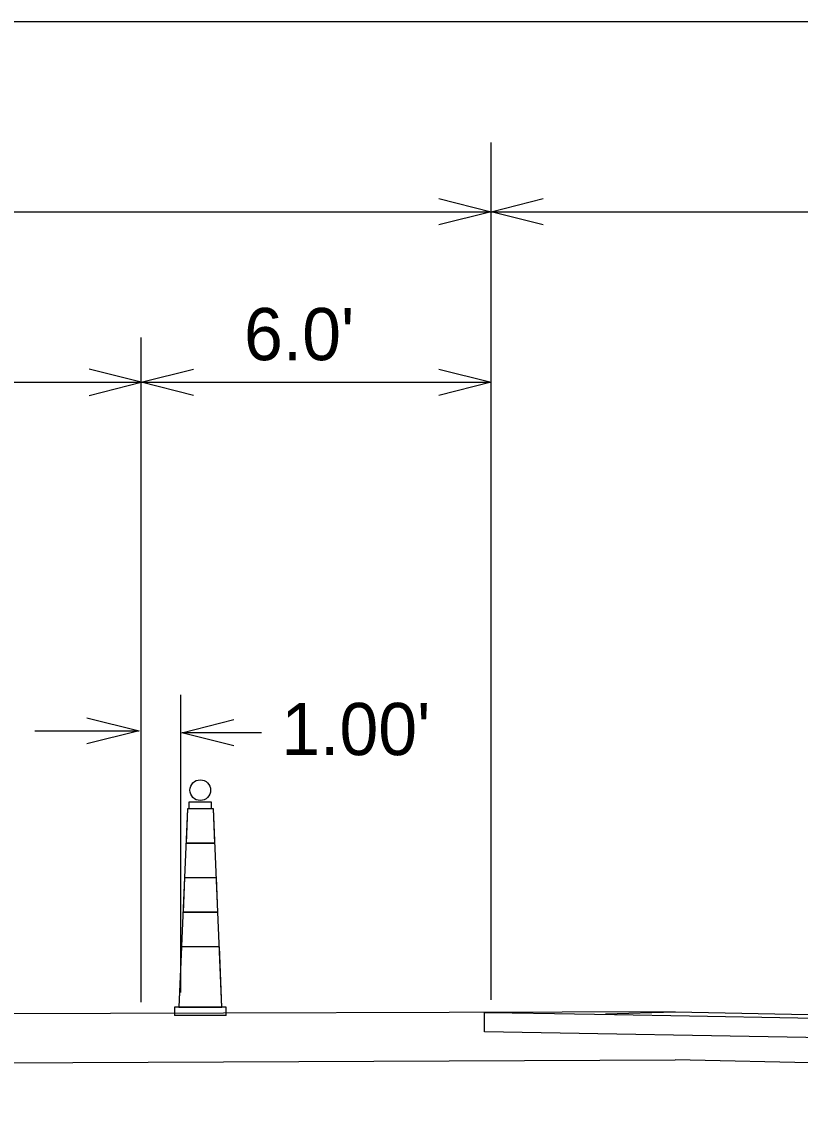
# Model space of a CAD drawing. Extents: x 10133 to 81668, y 4692 to 11018.
# Drawn here: x 29468.4 to 29807.5, y 5951 to 6420.8 of the extents above; entities that cross this region are included whole.
import ezdxf

# ---------------------------------------------------------------- set-up
doc = ezdxf.new("R2010")
doc.units = 0
for name, color, linetype in [('Level 7', 7, 'Continuous'), ('PavementRemovalStage1', 7, 'Continuous'), ('Stage_Construction Traffic Control', 7, 'Continuous')]:
    doc.layers.add(name, color=color, linetype=linetype)

msp = doc.modelspace()

# ---------------------------------------------------------------- linework, layer by layer
at = {"layer": 'Level 7'}
for p, q in [((28720.67, 6420.77), (30624.93, 6420.77)), ((29672.8, 5995.19), (29672.8, 6368.21)), ((28720.67, 6338.05), (29672.8, 6338.05)), ((28879.42, 6338.05), (29672.8, 6338.05)), ((29672.8, 6338.05), (30624.93, 6338.05)), ((29520.54, 5994.2), (29520.54, 6283.36)), ((29295.04, 6263.84), (29672.8, 6263.84)), ((29537.75, 5998.41), (29537.75, 6127.84)), ((29474.13, 6112.15), (29519.55, 6112.15)), ((29572.86, 6111.38), (29538.17, 6111.38)), ((29722.56, 5989.14), (29752.89, 5989.91)), ((28779.45, 5964.82), (29752.89, 5969)), ((30566.15, 5950.97), (29752.89, 5969))]:
    msp.add_line(p, q, dxfattribs=at)
for points in [[(29650.09, 6343.73), (29672.8, 6338.05), (29650.09, 6332.38)], [(29695.51, 6332.38), (29672.8, 6338.05), (29695.51, 6343.73)], [(29497.83, 6258.16), (29520.54, 6263.84), (29497.83, 6269.52)], [(29543.25, 6258.16), (29520.54, 6263.84), (29543.25, 6269.52)], [(29650.09, 6269.52), (29672.8, 6263.84), (29650.09, 6258.16)], [(29496.84, 6117.83), (29519.55, 6112.15), (29496.84, 6106.48)], [(29560.88, 6105.7), (29538.17, 6111.38), (29560.88, 6117.06)]]:
    msp.add_lwpolyline(points, dxfattribs=at)
at = {"layer": 'PavementRemovalStage1'}
for p, q in [((29752.89, 5989.91), (28720.67, 5987.21)), ((29669.91, 5981.22), (29669.92, 5985.7)), ((29752.89, 5989.91), (30624.93, 5973.37)), ((30100.93, 5973.7), (29669.91, 5981.22))]:
    msp.add_line(p, q, dxfattribs=at)
msp.add_lwpolyline([(29669.92, 5985.7), (29669.95, 5989.69), (29681.97, 5989.48), (29700.48, 5989.17), (29726.48, 5988.72), (29759.21, 5988.16), (29806.37, 5987.36), (29871.61, 5986.24), (29906.06, 5985.65), (30103.23, 5982.29)], dxfattribs=at)
at = {"layer": 'Stage_Construction Traffic Control'}
for p, q in [((29540.67, 6078.28), (29536.92, 5992.03)), ((29540.67, 6078.28), (29540.02, 6063.28)), ((29551.92, 6078.28), (29540.67, 6078.28)), ((29551.92, 6078.28), (29540.67, 6078.28)), ((29555.67, 5992.03), (29551.92, 6078.28)), ((29552.57, 6063.28), (29551.92, 6078.28)), ((29552.57, 6063.28), (29540.02, 6063.28)), ((29540.02, 6063.28), (29552.57, 6063.28)), ((29539.37, 6048.28), (29538.71, 6033.28)), ((29553.23, 6048.28), (29539.37, 6048.28)), ((29553.23, 6048.28), (29539.37, 6048.28)), ((29553.88, 6033.28), (29553.23, 6048.28)), ((29553.88, 6033.28), (29538.71, 6033.28)), ((29538.71, 6033.28), (29553.88, 6033.28)), ((29538.06, 6018.28), (29536.92, 5992.03)), ((29554.53, 6018.28), (29538.06, 6018.28)), ((29554.53, 6018.28), (29538.06, 6018.28)), ((29555.67, 5992.03), (29554.53, 6018.28)), ((29557.55, 5992.03), (29535.05, 5992.03)), ((29535.05, 5992.03), (29535.05, 5988.28)), ((29536.92, 5992.03), (29555.67, 5992.03)), ((29557.55, 5988.28), (29557.55, 5992.03)), ((29557.55, 5988.28), (29535.05, 5988.28))]:
    msp.add_line(p, q, dxfattribs=at)
msp.add_lwpolyline([(29541.42, 6081.28), (29551.02, 6081.28), (29551.02, 6078.28), (29541.42, 6078.28)], close=True, dxfattribs=at)
msp.add_circle((29546.22, 6086.38), 4.5, dxfattribs=at)

# ---------------------------------------------------------------- texts
at = {"layer": 'Level 7'}
for s, p in [("6.0'", (29565.26, 6273.46)), ("1.00'", (29581.49, 6101.63))]:
    msp.add_text(s, height=22.709, dxfattribs=at).set_placement(p)

doc.saveas('drawing.dxf')
